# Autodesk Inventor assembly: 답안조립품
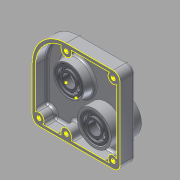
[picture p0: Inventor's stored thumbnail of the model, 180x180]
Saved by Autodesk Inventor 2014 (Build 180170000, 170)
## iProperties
Created: 2015-10
Part Number: 답안조립품
Document SubType Name: Assembly
Designer: youjin16
Author: youjin16
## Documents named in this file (4)
- C:\Users\youjin16\Desktop\451019V1011\답안조립품.iam
- C:\Users\youjin16\Desktop\451019V1011\본체.ipt
- C:\Users\youjin16\Desktop\451019V1011\앞커버.ipt
- C:\Users\youjin16\Desktop\451019V1011\베어링 6002.ipt
